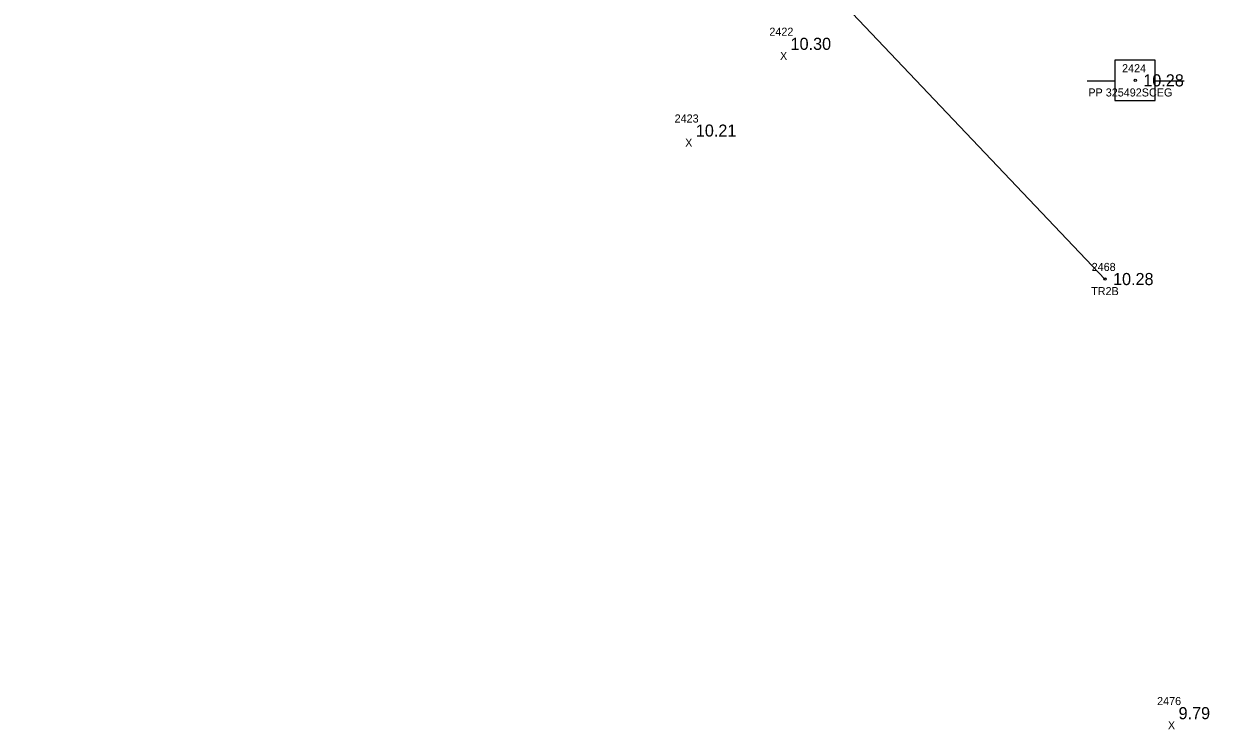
# Model space of a CAD drawing. Extents: x 2042117 to 2045853, y 303080 to 309569.
# Drawn here: x 2044355.6 to 2044502.6, y 304504.5 to 304592 of the extents above; entities that cross this region are included whole.
import ezdxf

# ---------------------------------------------------------------- set-up
doc = ezdxf.new("R2010")
doc.units = 0
for name, color, linetype in [('RD_EX_Misc_txCode', 7, 'Continuous'), ('RD_EX_TX_Misc_ELEV', 7, 'Continuous'), ('RD_EX_TX_VEG_ELEV', 7, 'Continuous'), ('RD_EX_UT', 7, 'Continuous'), ('RD_EX_UT_txCode', 7, 'Continuous'), ('RD_EX_VEG', 7, 'Continuous'), ('RD_EX_VEG_txCode', 7, 'Continuous'), ('RD_HC_Survey_ELEV', 7, 'Continuous'), ('RD_SMD_Locator', 7, 'Continuous')]:
    doc.layers.add(name, color=color, linetype=linetype)

msp = doc.modelspace()

# ---------------------------------------------------------------- linework, layer by layer
at = {"layer": 'RD_EX_UT'}
for p, q in [((2044495.88, 304587.53), (2044490.88, 304587.53)), ((2044490.88, 304587.53), (2044490.88, 304582.53)), ((2044495.88, 304582.53), (2044495.88, 304587.53)), ((2044487.45, 304584.97), (2044490.92, 304584.97)), ((2044495.81, 304584.97), (2044499.45, 304584.97)), ((2044490.88, 304582.53), (2044495.88, 304582.53))]:
    msp.add_line(p, q, dxfattribs=at)
at = {"layer": 'RD_EX_VEG'}
msp.add_lwpolyline([(2043442.97, 305737.07), (2043459.87, 305757.29), (2043500.33, 305735.55), (2043510.29, 305716.16), (2043558.94, 305666.15), (2043625.65, 305592.92), (2043688.91, 305518.94), (2043753.11, 305437.19), (2043818.03, 305364.7), (2043877.83, 305282.82), (2043938.63, 305211.62), (2044011.48, 305138.99), (2044075.86, 305057.44), (2044138.75, 304984.38), (2044203.27, 304905.13), (2044266.06, 304829.27), (2044328.58, 304748.23), (2044394.11, 304672.51), (2044456.79, 304595.02), (2044489.64, 304560.38)], dxfattribs=at)
at = {"layer": 'RD_SMD_Locator'}
for centre in [(2044493.39, 304585.02), (2044489.64, 304560.38)]:
    msp.add_circle(centre, 0.15, dxfattribs=at)

# ---------------------------------------------------------------- texts
at = {"layer": 'RD_EX_Misc_txCode'}
for s, p in [('2422', (2044448.05, 304590.55)), ('X', (2044449.37, 304587.55)), ('2423', (2044436.31, 304579.79)), ('X', (2044437.62, 304576.79)), ('2476', (2044496.1, 304507.54)), ('X', (2044497.44, 304504.54))]:
    msp.add_text(s, height=1, dxfattribs=at).set_placement(p)
at = {"layer": 'RD_EX_TX_Misc_ELEV'}
for s, p in [('10.30', (2044450.68, 304588.8)), ('10.21', (2044438.94, 304578.04)), ('9.79', (2044498.76, 304505.79))]:
    msp.add_text(s, height=1.5, dxfattribs=at).set_placement(p)
at = {"layer": 'RD_EX_TX_VEG_ELEV'}
msp.add_text('10.28', height=1.5, dxfattribs=at).set_placement((2044490.64, 304559.63))
at = {"layer": 'RD_EX_UT_txCode'}
for s, p in [('2424', (2044491.76, 304586.02)), ('PP 325492SCEG', (2044487.58, 304583.02))]:
    msp.add_text(s, height=1, dxfattribs=at).set_placement(p)
at = {"layer": 'RD_EX_VEG_txCode'}
for s, p in [('2468', (2044487.99, 304561.38)), ('TR2B', (2044487.93, 304558.38))]:
    msp.add_text(s, height=1, dxfattribs=at).set_placement(p)
at = {"layer": 'RD_HC_Survey_ELEV'}
msp.add_text('10.28', height=1.5, dxfattribs=at).set_placement((2044494.39, 304584.27))

doc.saveas('drawing.dxf')
